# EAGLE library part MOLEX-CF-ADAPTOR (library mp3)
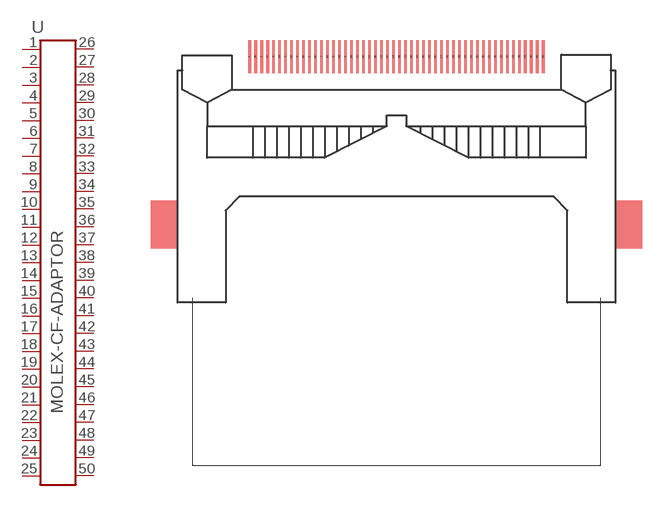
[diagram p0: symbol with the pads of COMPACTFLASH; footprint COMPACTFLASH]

Designator prefix -

## MOLEX-CF-ADAPTOR50P  [COMPACTFLASH]
1  1  pas
2  2  pas
3  3  pas
4  4  pas
5  5  pas
6  6  pas
7  7  pas
8  8  pas
9  9  pas
10  10  pas
11  11  pas
12  12  pas
13  13  pas
14  14  pas
15  15  pas
16  16  pas
17  17  pas
18  18  pas
19  19  pas
20  20  pas
21  21  pas
22  22  pas
23  23  pas
24  24  pas
25  25  pas
26  26  pas
27  27  pas
28  28  pas
29  29  pas
30  30  pas
31  31  pas
32  32  pas
33  33  pas
34  34  pas
35  35  pas
36  36  pas
37  37  pas
38  38  pas
39  39  pas
40  40  pas
41  41  pas
42  42  pas
43  43  pas
44  44  pas
45  45  pas
46  46  pas
47  47  pas
48  48  pas
49  49  pas
50  50  pas

## Footprint COMPACTFLASH (pad centres in mm)
smd 0.3 x 3.5: 1 -16.828,10.335; 2 -15.557,10.335; 3 -14.287,10.335; 4 -13.018,10.335; 5 -11.748,10.335; 6 -10.477,10.335; 7 -9.207,10.335; 8 -7.938,10.335; 9 -6.668,10.335; 10 -5.397,10.335; 11 -4.128,10.335; 12 -2.857,10.335; 13 -1.587,10.335; 14 -0.318,10.335; 15 0.953,10.335; 16 2.223,10.335; 17 3.493,10.335; 18 4.763,10.335; 19 6.032,10.335; 20 7.303,10.335; 21 8.572,10.335; 22 9.842,10.335; 23 11.113,10.335; 24 12.383,10.335; 25 13.652,10.335; 26 -16.192,10.335; 27 -14.922,10.335; 28 -13.652,10.335; 29 -12.383,10.335; 30 -11.113,10.335; 31 -9.842,10.335; 32 -8.572,10.335; 33 -7.303,10.335; 34 -6.032,10.335; 35 -4.763,10.335; 36 -3.493,10.335; 37 -2.223,10.335; 38 -0.953,10.335; 39 0.318,10.335; 40 1.587,10.335; 41 2.857,10.335; 42 4.128,10.335; 43 5.397,10.335; 44 6.668,10.335; 45 7.938,10.335; 46 9.207,10.335; 47 10.477,10.335; 48 11.748,10.335; 49 13.018,10.335; 50 14.287,10.335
